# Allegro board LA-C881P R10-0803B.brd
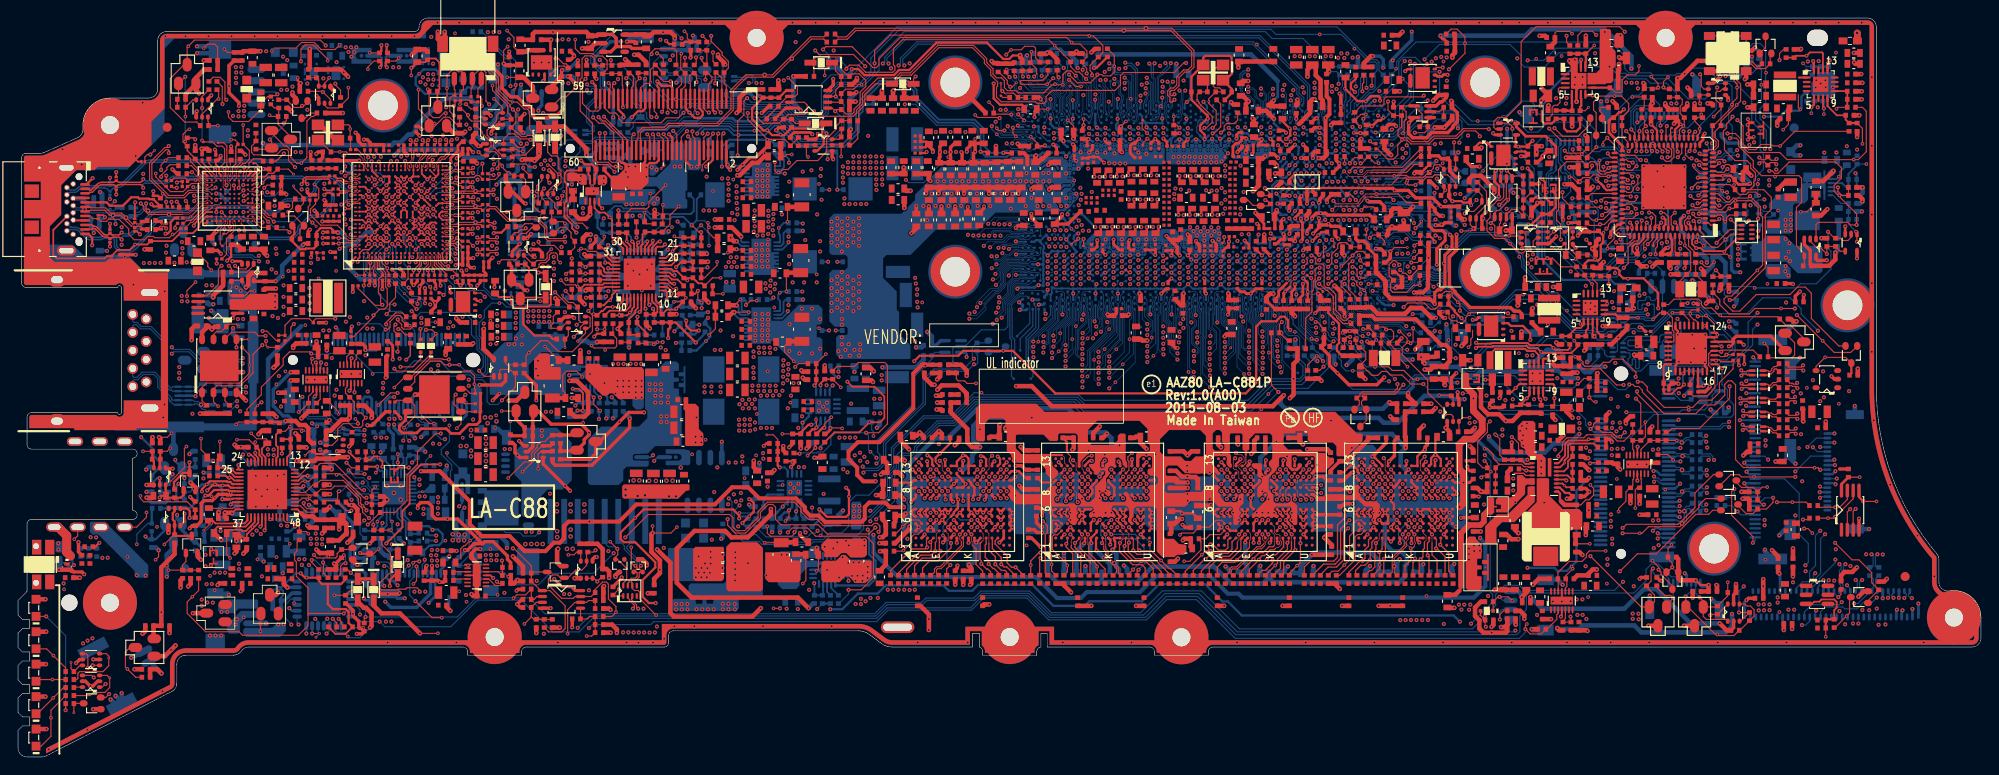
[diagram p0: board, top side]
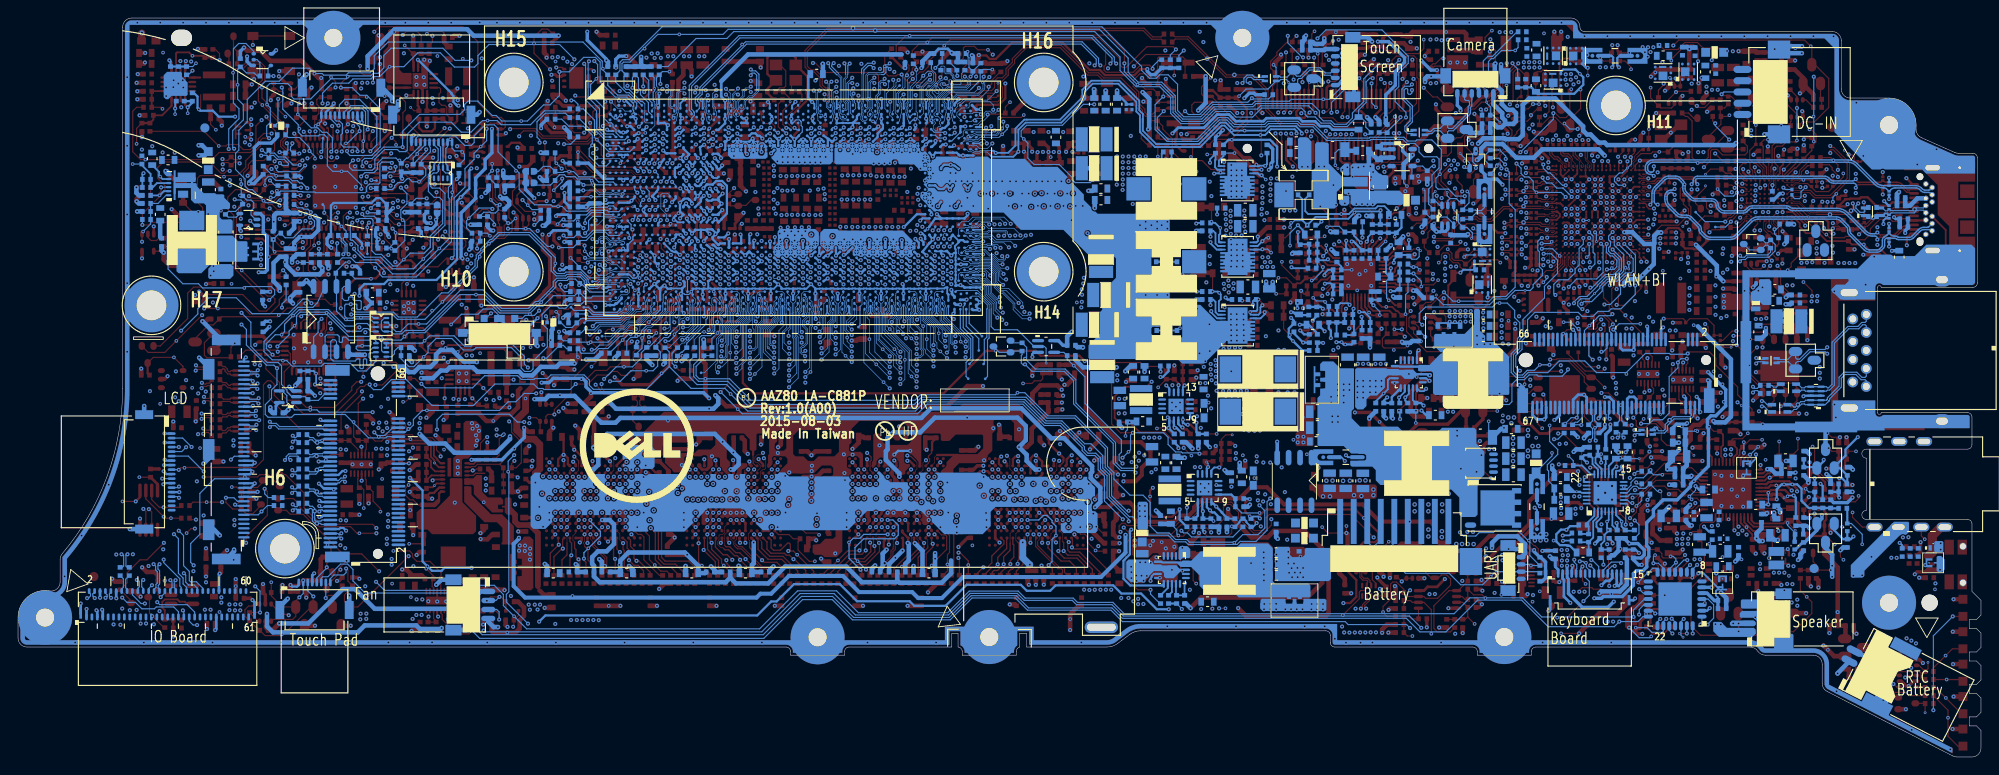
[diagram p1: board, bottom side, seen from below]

Outline 217.81 x 82 mm; copper layers: TOP, GND1, IN1, GND2, IN2, IN3, VCC, IN4, GND3, BOTTOM. Coordinates in mm from the lower left corner of the outline.
Outline path: 0,17.38 1,18.38 1,25.86 arc(1.15,26.21) 1.5,26.36 12.72,26.36 arc(13.22,26.86) 12.72,27.36 12.72,33.16 arc(13.22,33.66) 12.72,34.16 1.5,34.16 arc(1.15,34.31) 1,34.66 1,37.71 arc(1.15,38.06) 1.5,38.21 11.07,38.21 arc(11.27,38.01) 11.47,38.21 11.47,52.11 arc(11.27,52.31) 11.07,52.11 0.9,52.11 arc(0.55,52.26) 0.4,52.61 0.4,66.49 arc(0.55,66.84) 0.9,66.99 2.49,66.99 arc(2.7,67.01) 2.9,67.08 6.61,68.73 arc(7.04,69.09) 7.2,69.64 7.2,70.12 arc(8.08,72.24) 10.2,73.12 14.5,73.12 arc(15.21,73.41) 15.5,74.12 15.5,79.5 arc(15.79,80.21) 16.5,80.5 44,80.5 arc(44.35,80.65) 44.5,81 arc(44.79,81.71) 45.5,82 205.2,82 arc(205.91,81.71) 206.2,81 206.2,40.92 arc(207.93,31.15) 212.9,22.56 arc(213.08,22.26) 213.14,21.91 213.14,19.41 arc(213.49,18.65) 214.31,18.43 arc(216.75,17.76) 217.81,15.47 217.81,13.2 arc(217.52,12.49) 216.81,12.2 132.59,12.2 arc(132.24,12.05) 132.09,11.7 132.09,11.3 126.09,11.3 126.09,11.7 arc(125.94,12.05) 125.59,12.2 114.2,12.2 114.2,13.7 113.5,13.7 113.5,12.2 arc(113.17,12.04) 113.04,11.7 113.04,11.3 107.04,11.3 107.04,11.72 arc(106.94,12.02) 106.68,12.2 106.68,13.7 105.88,13.7 105.88,12.2 96.99,12.2 arc(96.36,12.3) 95.79,12.6 94.46,13.6 arc(93.89,13.9) 93.26,14 72.7,14 arc(72.35,13.85) 72.2,13.5 72.2,12.7 arc(72.05,12.35) 71.7,12.2 56.39,12.2 arc(56.04,12.05) 55.89,11.7 55.89,11.3 49.89,11.3 49.89,11.7 arc(49.74,12.05) 49.39,12.2 25.61,12.2 arc(25.14,12.08) 24.78,11.75 arc(24.41,11.42) 23.94,11.3 18.62,11.3 arc(17.91,11.01) 17.62,10.3 17.62,8.17 arc(17.47,7.65) 17.08,7.28 3.12,0.11 arc(2.89,0.03) 2.66,0 1,0 arc(0.29,0.29) 0,1 0,2.95 0.5,3.45 1.3,3.45 1.3,4.45 0.5,4.45 0,4.95 0,6.55 0.5,7.05 1.3,7.05 1.3,8.05 0.5,8.05 0,8.55 0,10.15 0.5,10.65 1.3,10.65 1.3,11.65 0.5,11.65 0,12.15 0,13.75 0.5,14.25 1.3,14.25 1.3,15.25 0.5,15.25 0,15.75 0,17.38

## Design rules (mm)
constraint set DEFAULT: min track width 0.127
net group 12C: nets I2C1_SDA I2C1_SDA_TP
net group CLK1_PCIE_WLAN: nets CLK1_PCIE_WLAN CLK1_PCIE_WLAN#
net group CLK_ITPXDP: nets CLK_ITPXDP_N CLK_ITPXDP_P
net group CLK_PCIE_MMI: nets CLK_PCIE_MMI CLK_PCIE_MMI#
net group CLK_PCIE_SSD: nets CLK_PCIE_SSD CLK_PCIE_SSD#
net group CLKO_PCIE_TBT: nets CLK0_PCIE_TBT CLK0_PCIE_TBT#
net group CPU_DDI1_AUX: nets CPU_DDI1_AUXN CPU_DDI1_AUXP
net group CPU_DDI2_AUX: nets CPU_DDI2_AUXN CPU_DDI2_AUXP
net group DDI1_PTX_TBRX_P0: nets DDI1_PTX_TBRX_N0 DDI1_PTX_TBRX_P0
net group DDI1_PTX_TBRX_P1: nets DDI1_PTX_TBRX_N1 DDI1_PTX_TBRX_P1
net group DDI1_PTX_TBRX_P2: nets DDI1_PTX_TBRX_N2 DDI1_PTX_TBRX_P2
net group DDI1_PTX_TBRX_P3: nets DDI1_PTX_TBRX_N3 DDI1_PTX_TBRX_P3
net group DDI2_PTX_TBRX_P0: nets DDI2_PTX_TBRX_N0 DDI2_PTX_TBRX_P0
net group DDI2_PTX_TBRX_P1: nets DDI2_PTX_TBRX_N1 DDI2_PTX_TBRX_P1
net group DDI2_PTX_TBRX_P2: nets DDI2_PTX_TBRX_N2 DDI2_PTX_TBRX_P2
net group DDI2_PTX_TBRX_P3: nets DDI2_PTX_TBRX_N3 DDI2_PTX_TBRX_P3
net group DIFFPAIR0: nets EDP_AUXN EDP_AUXP
net group DIFFPAIR1: nets EDP_AUXN_C EDP_AUXP_C
net group DIFFPAIR2: nets EDP_AUXN_CONN EDP_AUXP_CONN
net group DIFFPAIR4: nets EDP_TXN_P2_C EDP_TXP_P2_C
net group DIFFPAIR5: nets EDP_TXN_P3_C EDP_TXP_P3_C
net group DIFFPAIR6: nets CPU_DDI1_AUXN_C CPU_DDI1_AUXP_C
net group DIFFPAIR7: nets CLK_ITPXDP_N_R CLK_ITPXDP_P_R
net group DIFFPAIR8: nets PCIE_PRX_TBTX_N1_C PCIE_PRX_TBTX_P1_C
net group DIFFPAIR9: nets PCIE_PRX_TBTX_N2_C PCIE_PRX_TBTX_P2_C
net group DIFFPAIR10: nets PCIE_PTX_CARDRX_N6_C PCIE_PTX_CARDRX_P6_C
net group DIFFPAIR11: nets PCIE_PTX_SSDRX_N11_C PCIE_PTX_SSDRX_P11_C
net group DIFFPAIR12: nets PCIE_PTX_SSDRX_N10_C PCIE_PTX_SSDRX_P10_C
net group DIFFPAIR13: nets PCIE_PTX_WLANRX_N5_C PCIE_PTX_WLANRX_P5_C
net group DIFFPAIR14: nets PCIE_PTX_SSDRX_N9_C PCIE_PTX_SSDRX_P9_C
net group DIFFPAIR15: nets PCIE_PTX_TBRX_N1_C PCIE_PTX_TBRX_P1_C
net group DIFFPAIR16: nets PCIE_PTX_TBRX_N2_C PCIE_PTX_TBRX_P2_C
net group DIFFPAIR17: nets USB20_N2_CONN USB20_P2_CONN
net group DIFFPAIR18: nets USB20_N3_R USB20_P3_R
net group DIFFPAIR19: nets USB20_N4_CONN USB20_P4_CONN
net group DIFFPAIR20: nets USB20_N5_CONN USB20_P5_CONN
net group DIFFPAIR21: nets USB3RN2_RC_CON USB3RP2_RC_CON
net group DIFFPAIR22: nets USB3TN2_C USB3TP2_C
net group DIFFPAIR23: nets USB3TN2_RC_CON USB3TP2_RC_CON
net group DIFFPAIR24: nets EDP_TXN_P0_C EDP_TXP_P0_C
net group DIFFPAIR25: nets EDP_TXN_P1_C EDP_TXP_P1_C
net group DP_CPU_DDI2_AUXN_C: nets CPU_DDI2_AUXN_C CPU_DDI2_AUXP_C
net group DP_EDP_TXN_P0_CONN: nets EDP_TXN_P0_CONN EDP_TXP_P0_CONN
net group DP_EDP_TXN_P1_CONN: nets EDP_TXN_P1_CONN EDP_TXP_P1_CONN
net group DP_EDP_TXN_P2_CONN: nets EDP_TXN_P2_CONN EDP_TXP_P2_CONN
net group DP_EDP_TXN_P3_CONN: nets EDP_TXN_P3_CONN EDP_TXP_P3_CONN
net group DP_TBT_I2C_B_N_R: nets TBT_I2C_B_N_R TBT_I2C_B_P_R
net group DP_TBT_USB2_T_N_R: nets TBT_USB2_T_N_R TBT_USB2_T_P_R
net group EDP_TX_P1: nets EDP_TXN_P1 EDP_TXP_P1
net group EDP_TX_P2: nets EDP_TXN_P2 EDP_TXP_P2
net group EDP_TX_P3: nets EDP_TXN_P3 EDP_TXP_P3
net group EPD_TX_P0: nets EDP_TXN_P0 EDP_TXP_P0
net group MEM_SMBCLKDATA: nets MEM_SMBCLK MEM_SMBDATA
net group PBAT_SMBCLKDAT: nets PBAT_SMBCLK PBAT_SMBDAT
net group PCIE_PRX_CARDTX_P6: nets PCIE_PRX_CARDTX_N6 PCIE_PRX_CARDTX_P6
net group PCIE_PRX_SSDTX_11: nets PCIE_PRX_SSDTX_N11 PCIE_PRX_SSDTX_P11
net group PCIE_PRX_SSDTX_P9: nets PCIE_PRX_SSDTX_N9 PCIE_PRX_SSDTX_P9
net group PCIE_PRX_SSDTX_P10: nets PCIE_PRX_SSDTX_N10 PCIE_PRX_SSDTX_P10
net group PCIE_PRX_TBTX_P1: nets PCIE_PRX_TBTX_N1 PCIE_PRX_TBTX_P1
net group PCIE_PRX_TBTX_P2: nets PCIE_PRX_TBTX_N2 PCIE_PRX_TBTX_P2
net group PCIE_PRX_WLANTX_P5: nets PCIE_PRX_WLANTX_N5 PCIE_PRX_WLANTX_P5
net group PCIE_PTX_CARDRX_P6: nets PCIE_PTX_CARDRX_N6 PCIE_PTX_CARDRX_P6
net group PCIE_PTX_SSDRX_11: nets PCIE_PTX_SSDRX_N11 PCIE_PTX_SSDRX_P11
net group PCIE_PTX_SSDRX_P9: nets PCIE_PTX_SSDRX_N9 PCIE_PTX_SSDRX_P9
net group PCIE_PTX_SSDRX_P10: nets PCIE_PTX_SSDRX_N10 PCIE_PTX_SSDRX_P10
net group PCIE_PTX_TBRX_P1: nets PCIE_PTX_TBRX_N1 PCIE_PTX_TBRX_P1
net group PCIE_PTX_TBRX_P2: nets PCIE_PTX_TBRX_N2 PCIE_PTX_TBRX_P2
net group PCIE_PTX_WLANRX_P5: nets PCIE_PTX_WLANRX_N5 PCIE_PTX_WLANRX_P5
net group REM_DIODE1: nets REM_DIODE1_N REM_DIODE1_P
net group REM_DIODE2: nets REM_DIODE2_N REM_DIODE2_P
net group REM_DIODE3: nets REM_DIODE3_N REM_DIODE3_P
net group REM_DIODE4: nets REM_DIODE4_N REM_DIODE4_P
net group SATA_PRX_SSDTX_2: nets SATA_PRX_SSDTX_N2 SATA_PRX_SSDTX_P2
net group SATA_PTX_SSDRX_2: nets SATA_PTX_SSDRX_N2 SATA_PTX_SSDRX_P2
net group SMB_CLKDAT: nets CLK_SMB DAT_SMB
net group SML1_SMBCLKDAT: nets SML1_SMBCLK SML1_SMBDAT
net group SPACING-18: nets PECI_EC PECI_EC_R
net group TBT_12C_CLKDATA: nets TBT_I2C_CLK TBT_I2C_DATA
net group TBT_I2C_B: nets TBT_I2C_B_N TBT_I2C_B_P
net group TBT_USB2_T: nets TBT_USB2_T_N TBT_USB2_T_P
net group TBT_USB3_RX1: nets TBT_USB3_RX1_N TBT_USB3_RX1_P
net group TBT_USB3_TX1: nets TBT_USB3_TX1_N TBT_USB3_TX1_P
net group TBT_USB3_TXO_P: nets TBT_USB3_TX0_N TBT_USB3_TX0_P
net group USB2.0_P1: nets USB20_N1 USB20_P1
net group USB2.0_P2: nets USB20_N2 USB20_P2
net group USB2.0_P3: nets USB20_N3 USB20_P3
net group USB2.0_P4: nets USB20_N4 USB20_P4
net group USB2.0_P5: nets USB20_N5 USB20_P5
net group USB3.0_R1: nets USB3RN1 USB3RP1
net group USB3.0_R2: nets USB3RN2 USB3RP2
net group USB3.0_T1: nets USB3TN1 USB3TP1
net group USB3.0_T2: nets USB3TN2 USB3TP2
net group USB_2.0: nets TBT_USB2_D_N TBT_USB2_D_P
net group 12C_15: nets HDA_BIT_CLK HDA_BIT_CLK_R I2C1_SCK I2C1_SCK_TP PCH_SPI_CLK PCH_SPI_CLK_TPM SPI_CLK_VROM
net group 24MHZ: nets CLK_LPC_DEBUG CLK_PCI_MEC PCI_CLK_LPC0 PCI_CLK_LPC1 XTAL24_IN XTAL24_OUT
net group AR_TBT: nets TBT_USB3_TX0_N_C TBT_USB3_TX0_P_C TBT_USB3_TX1_N_C TBT_USB3_TX1_P_C
net group COMP-20-25: nets SM_RCOMP0 SM_RCOMP1 SM_RCOMP2
net group DDRA_CKE: nets DDR_A_CKE0 DDR_A_CKE1 DDR_A_CKE2 DDR_A_CKE3
net group DDRB-D6: nets DDR_B_D48 DDR_B_D49 DDR_B_D50 DDR_B_D51 DDR_B_D52 DDR_B_D53 DDR_B_D54 DDR_B_D55
net group DDRB-D7: nets DDR_B_D56 DDR_B_D57 DDR_B_D58 DDR_B_D59 DDR_B_D60 DDR_B_D61 DDR_B_D62 DDR_B_D63
net group DDRB_CKE: nets DDR_B_CKE0 DDR_B_CKE1 DDR_B_CKE2 DDR_B_CKE3
net group DP1_AR_TBT: nets DDI1_PTX_TBRX_N0_C DDI1_PTX_TBRX_N1_C DDI1_PTX_TBRX_N2_C DDI1_PTX_TBRX_N3_C DDI1_PTX_TBRX_P0_C DDI1_PTX_TBRX_P1_C DDI1_PTX_TBRX_P2_C DDI1_PTX_TBRX_P3_C
net group DP2_AR_TBT: nets DDI2_PTX_TBRX_N0_C DDI2_PTX_TBRX_N1_C DDI2_PTX_TBRX_N2_C DDI2_PTX_TBRX_N3_C DDI2_PTX_TBRX_P0_C DDI2_PTX_TBRX_P1_C DDI2_PTX_TBRX_P2_C DDI2_PTX_TBRX_P3_C
net group HDA: nets HDA_SDIN0 HDA_SDOUT HDA_SDOUT_R HDA_SYNC HDA_SYNC_R
net group R_DDRA-CLK-UD19: nets DDR_A_DQS0 DDR_A_DQS1 DDR_A_DQS2 DDR_A_DQS3
net group R_DDRA-CLK-UD20: nets DDR_A_DQS4 DDR_A_DQS5 DDR_A_DQS6 DDR_A_DQS7
net group R_DDRA-D0: nets DDR_A_D0 DDR_A_D1 DDR_A_D2 DDR_A_D3 DDR_A_D4 DDR_A_D5 DDR_A_D6 DDR_A_D7
net group R_DDRA-D1: nets DDR_A_D8 DDR_A_D9 DDR_A_D10 DDR_A_D11 DDR_A_D12 DDR_A_D13 DDR_A_D14 DDR_A_D15
net group R_DDRA-D2: nets DDR_A_D16 DDR_A_D17 DDR_A_D18 DDR_A_D19 DDR_A_D20 DDR_A_D21 DDR_A_D22 DDR_A_D23
net group R_DDRA-D3: nets DDR_A_D24 DDR_A_D25 DDR_A_D26 DDR_A_D27 DDR_A_D28 DDR_A_D29 DDR_A_D30 DDR_A_D31
net group R_DDRA-D4: nets DDR_A_D32 DDR_A_D33 DDR_A_D34 DDR_A_D35 DDR_A_D36 DDR_A_D37 DDR_A_D38 DDR_A_D39
net group R_DDRA-D5: nets DDR_A_D40 DDR_A_D41 DDR_A_D42 DDR_A_D43 DDR_A_D44 DDR_A_D45 DDR_A_D46 DDR_A_D47
net group R_DDRA-D6: nets DDR_A_D48 DDR_A_D49 DDR_A_D50 DDR_A_D51 DDR_A_D52 DDR_A_D53 DDR_A_D54 DDR_A_D55
net group R_DDRA-D7: nets DDR_A_D56 DDR_A_D57 DDR_A_D58 DDR_A_D59 DDR_A_D60 DDR_A_D61 DDR_A_D62 DDR_A_D63
net group R_DDRA-DQS0: nets DDR_A_DQS#0
net group R_DDRA-DQS1: nets DDR_A_DQS#1
net group R_DDRA-DQS2: nets DDR_A_DQS#2
net group R_DDRA-DQS3: nets DDR_A_DQS#3
net group R_DDRA-DQS4: nets DDR_A_DQS#4
net group R_DDRA-DQS5: nets DDR_A_DQS#5
net group R_DDRA-DQS6: nets DDR_A_DQS#6
net group R_DDRA-DQS7: nets DDR_A_DQS#7
net group R_DDRB-CLK-UD21: nets DDR_B_DQS0 DDR_B_DQS1 DDR_B_DQS2 DDR_B_DQS3
net group R_DDRB-CLK-UD22: nets DDR_B_DQS4 DDR_B_DQS5 DDR_B_DQS6 DDR_B_DQS7
net group R_DDRB-D0: nets DDR_B_D0 DDR_B_D1 DDR_B_D2 DDR_B_D3 DDR_B_D4 DDR_B_D5 DDR_B_D6 DDR_B_D7
net group R_DDRB-D1: nets DDR_B_D8 DDR_B_D9 DDR_B_D10 DDR_B_D11 DDR_B_D12 DDR_B_D13 DDR_B_D14 DDR_B_D15
net group R_DDRB-D2: nets DDR_B_D16 DDR_B_D17 DDR_B_D18 DDR_B_D19 DDR_B_D20 DDR_B_D21 DDR_B_D22 DDR_B_D23
net group R_DDRB-D3: nets DDR_B_D24 DDR_B_D25 DDR_B_D26 DDR_B_D27 DDR_B_D28 DDR_B_D29 DDR_B_D30 DDR_B_D31
net group R_DDRB-D4: nets DDR_B_D32 DDR_B_D33 DDR_B_D34 DDR_B_D35 DDR_B_D36 DDR_B_D37 DDR_B_D38 DDR_B_D39
net group R_DDRB-D5: nets DDR_B_D40 DDR_B_D41 DDR_B_D42 DDR_B_D43 DDR_B_D44 DDR_B_D45 DDR_B_D46 DDR_B_D47
net group R_DDRB-DQS0: nets DDR_B_DQS#0
net group R_DDRB-DQS1: nets DDR_B_DQS#1
net group R_DDRB-DQS2: nets DDR_B_DQS#2
net group R_DDRB-DQS3: nets DDR_B_DQS#3
net group R_DDRB-DQS4: nets DDR_B_DQS#4
net group R_DDRB-DQS5: nets DDR_B_DQS#5
net group R_DDRB-DQS6: nets DDR_B_DQS#6
net group R_DDRB-DQS7: nets DDR_B_DQS#7
net group SPACING-12: nets H_CATERR# H_PROCHOT# H_PROCHOT#_EC H_PROCHOT#_R H_THERMTRIP# H_VCCST_PWRGD PCIE_RCOMPN PCIE_RCOMPP VCCST_PWRGD XDP_OBS0 XDP_OBS0_R XDP_OBS1 XDP_OBS1_R XDP_OBS2_R XDP_OBS3_R
net group SPACING-15: nets DMIC_CLK_CODEC DMIC_CLK_CODEC_R PCH_RTCRST# PCH_RTCX1 PCH_RTCX2 SRTCRST# USBCOMP XCLK_BIASREF
net group SPACING-20: nets +V_DDR_REF_CA +V_DDR_REFA_R +V_DDR_REFB_R +VREFDQ_A +VREFDQ_B N40373163 N40373501 N40376778
net group SPACING-25: nets EDP_COMP
net group SPI_PCH: nets PCH_SPI_CS0# PCH_SPI_DO2_XDP PCH_SPI_DO_XDP PCH_SPI_IO2 PCH_SPI_IO3 PCH_SPI_SI PCH_SPI_SI_TPM PCH_SPI_SO PCH_SPI_SO_TPM RESET_OUT#_R SPI_IO2_VROM SPI_IO3_VROM SPI_SI_VROM SPI_SO_VROM
net group UART: nets UART0_TX
net group W20: nets +3V_VC +AVDD2 +DVDD ALW_PWRGD_3V_5V BATBTN# BATDRV#
nets with their own width: min track width 0.127; nets +1.8VA +3VLP +3VS_AUDIO
nets with their own width: min track width 0.508; nets GND

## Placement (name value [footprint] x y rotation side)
C2  15P_0402_50V8J  [C_0402]  27.28 50.94 90 top
C3  15P_0402_50V8J  [C_0402]  20.09 51.27 0 bottom
C4  15P_0402_50V8J  [C_0402]  54.45 70.27 0 bottom
C5  15P_0402_50V8J  [C_0402]  74.4 78.44 0 bottom
C6  15P_0402_50V8J  [C_0402]  193.09 33.87 180 top
C7  15P_0402_50V8J  [C_0402]  186.74 18.37 180 top
C8  2.2U_0603_6.3V6K~D  [C_0603]  63.48 80.03 270 top
C94  10U_0603_6.3V6M  [C_0603]  181.46 44.54 180 top
C95  0.1U_0201_10V6K  [C_0201]  186.41 41.11 270 top
C96  0.1U_0201_10V6K  [C_0201]  190.31 46.06 0 top
C97  0.1U_0201_10V6K  [C_0201]  181.17 47.23 180 top
C98  0.1U_0201_10V6K  [C_0201]  182.6 40.73 0 top
C135  0.1U_0201_10V6K  [C_0201]  190.31 44.66 0 top
C265  .1U_0402_16V7K~D  [C_0402]  20.09 50.38 0 bottom
C303  150U_B2_6.3VM_ESR35M  [C_B2]  19.94 48.35 180 bottom
C352  0.1U_0402_10V7K  [C_0402]  46.63 16.85 0 top
C355  2200P_0402_25V7K~D  [C_0402]  48.31 19.59 180 top
C375  0.1U_0402_25V6K~D  [C_0402]  45.95 20.48 270 top
C376  0.1U_0402_25V6K~D  [C_0402]  47.22 21.98 90 bottom
C377  0.1U_0402_25V6K~D  [C_0402]  45.06 20.48 270 top
C397  0.47U_0402_25V6K  [C_0402]  9.32 61.17 180 bottom
C398  0.47U_0402_25V6K  [C_0402]  9.02 58.82 180 bottom
C401  0.47U_0402_25V6K  [C_0402]  9.02 59.71 180 bottom
C402  0.47U_0402_25V6K  [C_0402]  9.32 62.06 180 bottom
C612  0.1U_0402_25V6K~D  [C_0402]  196.2 25.1 90 top
C613  0.1U_0402_25V6K~D  [C_0402]  199.67 15.2 0 top
C614  0.1U_0402_25V6K~D  [C_0402]  197.21 50.5 0 top
C615  0.1U_0402_25V6K~D  [C_0402]  196.06 52.54 180 top
C616  0.1U_0402_25V6K~D  [C_0402]  190.63 48.09 270 bottom
C617  0.1U_0402_25V6K~D  [C_0402]  190.67 50.71 90 bottom
C618  0.22U_0201_6.3V6M  [C_0201]  18.29 59.81 180 top
C621  0.1U_0402_10V7K  [C_0402]  24.49 40.34 180 bottom
C623  0.1U_0402_10V7K  [C_0402]  24.49 41.23 180 bottom
C712  22U_0603_6.3V6M~D  [C_0603]  33.12 46.82 270 top
C713  0.1U_0402_10V7K  [C_0402]  48.87 46.69 270 top
C715  0.1U_0402_10V7K  [C_0402]  31.09 46.82 270 top
C716  22U_0603_6.3V6M~D  [C_0603]  47.73 46.69 270 top
C719  4.7U_0603_6.3V6K  [C_0603]  175.43 25.61 180 top
C720  .1U_0402_16V7K~D  [C_0402]  175.18 28.03 180 top
C721  0.01U_0402_16V7K~D  [C_0402]  176.12 41.55 180 top
C722  47P_0402_50V8J~D  [C_0402]  175.18 26.76 180 top
C962  10U_0603_6.3V6M~D  [C_0603]  26.14 50.06 270 top
C963  .1U_0402_16V7K~D  [C_0402]  27.28 50.07 270 top
C1060  0.1U_0402_10V7K  [C_0402]  196.32 37.42 180 top
C1061  0.1U_0402_10V7K  [C_0402]  196.32 39.2 180 top
C1062  0.1U_0402_10V7K  [C_0402]  196.32 38.31 180 top
C1063  0.1U_0402_10V7K  [C_0402]  196.32 40.09 180 top
C1064  0.1U_0402_10V7K  [C_0402]  196.32 36.53 180 top
C1065  0.1U_0402_10V7K  [C_0402]  196.32 35.65 180 top
C1066  0.1U_0402_10V7K  [C_0402]  196.32 41.87 180 top
C1067  0.1U_0402_10V7K  [C_0402]  196.32 40.98 180 top
C1068  0.1U_0402_10V7K  [C_0402]  196.32 43.65 180 top
C1069  0.1U_0402_10V7K  [C_0402]  196.32 42.76 180 top
C1102  0.1U_0402_25V6K~D  [C_0402]  166.17 15.33 180 top
C1143  10U_0603_6.3V6M~D  [C_0603]  195.81 34.18 270 top
C1145  .1U_0402_16V7K~D  [C_0402]  193.09 34.76 180 top
C1158  1U_0402_6.3V6K~D  [C_0402]  177.52 33.44 270 top
C1159  0.1U_0402_10V7K  [C_0402]  167.82 17.1 180 top
C1160  1U_0402_6.3V6K~D  [C_0402]  37.82 39.91 270 top
C1161  0.1U_0402_10V7K  [C_0402]  181.79 26.88 180 top
C1162  1U_0402_6.3V6K~D  [C_0402]  181.97 33.56 270 top
C1163  1000P_0402_50V7K~D  [C_0402]  179.93 29.88 270 top
C1164  0.1U_0402_10V7K  [C_0402]  176.25 31.76 90 top
C1166  1U_0402_6.3V6K~D  [C_0402]  35.79 39.91 270 top
C1167  2200P_0402_25V7K~D  [C_0402]  36.99 44.93 90 top
C1168  1U_0402_6.3V6K~D  [C_0402]  198.02 39.56 270 top
C1169  1U_0402_6.3V6K~D  [C_0402]  30.96 42.71 270 top
C1199  1U_0402_6.3V6K~D  [C_0402]  51.23 22.31 180 top
C1200  0.1U_0402_10V7K  [C_0402]  47.14 22.89 0 top
C1201  1U_0402_6.3V6K~D  [C_0402]  51.87 17.87 180 top
C1203  1U_0402_6.3V6K~D  [C_0402]  60.35 78.32 0 top
C1204  0.1U_0402_10V7K  [C_0402]  60.3 75.51 0 top
C1205  2.2U_0603_6.3V6K~D  [C_0603]  24.28 28 0 bottom
C1208  0.1U_0402_10V7K  [C_0402]  57.13 79.59 0 top
C1211  0.1U_0402_10V7K  [C_0402]  199.67 36.53 0 top
C1212  1000P_0402_50V7K~D  [C_0402]  33.12 39.28 270 top
C1213  1U_0402_6.3V6K~D  [C_0402]  34.21 44.41 180 top
C1214  4700P_0402_25V7K  [C_0402]  32.23 39.28 270 top
C1215  0.1U_0402_10V7K  [C_0402]  34.27 46.64 270 top
C1216  0.1U_0402_10V7K  [C_0402]  41 45.22 90 top
C1217  0.1U_0402_10V7K  [C_0402]  29.57 39.51 90 top
C1218  0.1U_0402_10V7K  [C_0402]  34.27 37.12 270 top
C1220  1U_0402_6.3V6K  [C_0402]  54.5 76.76 90 top
C1221  1U_0402_6.3V6K~D  [C_0402]  54.45 69.31 0 bottom
C1222  1U_0402_6.3V6K~D  [C_0402]  74.4 79.33 0 bottom
C1223  1U_0402_6.3V6K~D  [C_0402]  68.56 80.17 270 top
C1225  1U_0402_6.3V6K~D  [C_0402]  187.6 18.37 0 top
C1226  680P_0402_50V7K~D  [C_0402]  181.84 19.01 90 top
C1229  680P_0402_50V7K~D  [C_0402]  180.7 19.01 90 top
C1254  1U_0402_6.3V6K~D  [C_0402]  169.14 16.21 270 top
C1256  1U_0402_6.3V6K~D  [C_0402]  173.2 14.97 270 top
C1257  2200P_0402_25V7K~D  [C_0402]  170.87 19.77 180 top
C1258  2200P_0402_25V7K~D  [C_0402]  171.73 19.77 0 top
C1264  0.1U_0402_10V7K  [C_0402]  175.18 20.15 180 top
C1273  0.1U_0402_25V6K~D  [C_0402]  69.84 38.88 180 bottom
C1274  0.1U_0402_25V6K~D  [C_0402]  58.84 57.03 90 bottom
C1275  0.1U_0402_25V6K~D  [C_0402]  73.19 39.65 0 top
C1278  220P_0402_50V8K  [C_0402]  48.31 20.48 180 top
C1279  220P_0402_50V8K  [C_0402]  15.8 61.1 90 top
C1280  220P_0402_50V8K  [C_0402]  14.71 57.25 270 top
C1289  0.1U_0402_10V7K  [C_0402]  27.41 52.79 90 top
C1292  2200P_0402_25V7K~D  [C_0402]  178.92 29.88 270 top
C1293  2200P_0402_25V7K~D  [C_0402]  37.88 44.93 90 top
C1297  15P_0402_50V8J  [C_0402]  31.98 46.82 270 top
C1298  15P_0402_50V8J  [C_0402]  49.76 46.69 270 top
C1301  15P_0402_50V8J  [C_0402]  43.54 36.86 270 bottom
C1302  15P_0402_50V8J  [C_0402]  42.39 36.86 270 bottom
C1304  15P_0402_50V8J  [C_0402]  176.12 40.66 180 top
C1309  15P_0402_50V8J  [C_0402]  15.9 14.56 0 top
C1321  1U_0402_6.3V6K~D  [C_0402]  193.65 17.61 180 top
C1322  0.1U_0402_10V7K  [C_0402]  195.94 14.82 0 top
C1324  0.1U_0402_10V7K  [C_0402]  195.3 21.09 90 top
C1325  1U_0402_6.3V6K~D  [C_0402]  196.95 21.09 90 top
C1339  1U_0603_25V6  [C_0603]  20.23 57.24 180 top
C1341  4.7U_0603_25V6K  [C_0603]  27.79 61.17 0 top
C1345  1U_0201_6.3V6M  [C_0201]  20.42 66.25 90 top
C1346  10U_0402_6.3V6M  [C_0402]  20.88 47.84 180 top
C1347  22U_0603_6.3V6M  [C_0603]  21.34 57.61 270 top
C1348  22U_0603_6.3V6M  [C_0603]  24.84 57.74 270 top
C1349  22U_0603_6.3V6M  [C_0603]  27.28 57.74 270 top
C1350  22U_0603_6.3V6M  [C_0603]  26.06 57.74 270 top
C1353  1U_0603_25V6  [C_0603]  18.07 55.08 180 top
C1354  1U_0201_6.3V6M  [C_0201]  21.95 66.21 90 top
C2973  0.1U_0402_16V4Z  [C_0402]  14.66 9.74 180 top
C2982  10U_0603_25V6M  [C_0603]  197.27 24.54 90 top
C2983  0.1U_0402_10V7K  [C_0402]  5.23 19.9 0 top
CA2  10U_0805_10V6K  [C_0805]  28.08 22.82 0 bottom
CA3  0.1U_0402_16V7K~N  [C_0402]  26.9 23.28 270 bottom
CA4  0.1U_0402_16V7K~N  [C_0402]  33.12 26.32 270 top
CA5  10U_0805_10V6K  [C_0805]  35.95 26.37 0 top
CA6  10U_0805_10V6K  [C_0805]  32.65 33.36 0 bottom
CA7  0.1U_0402_16V7K~N  [C_0402]  33.05 31.96 0 bottom
CA23  10P_0402_50V8J~D  [C_0402]  36.37 28.28 180 top
CA24  10P_0402_50V8J~D  [C_0402]  33.96 32.09 180 top
CA25  10P_0402_50V8J~D  [C_0402]  33.96 27.39 180 top
CA27  10P_0402_50V8J~D  [C_0402]  33.96 29.17 180 top
CA28  100P_0402_50V8J~D  [C_0402]  6.96 23.15 270 bottom
CA29  100P_0402_50V8J~D  [C_0402]  19.69 22.89 90 bottom
CA30  10P_0402_50V8J~D  [C_0402]  33.96 30.18 180 top
CA31  0.1U_0402_10V7K  [C_0402]  34.9 26.32 270 top
CA32  100P_0402_50V8J~D  [C_0402]  111.86 76.08 90 bottom
CA33  100P_0402_50V8J~D  [C_0402]  28.07 37.17 90 top
CA34  0.1U_0402_10V7K  [C_0402]  28.99 37.05 270 top
CA35  100P_0402_50V8J~D  [C_0402]  111.81 73.19 0 top
CA40  0.1U_0402_25V6K~D  [C_0402]  15.79 33.92 90 top
CA42  2.2U_0402_6.3V6M  [C_0402]  34.01 26.32 270 top
CA53  1000P_0402_50V7K~D  [C_0402]  24.87 19.26 0 top
CA54  1000P_0402_50V7K~D  [C_0402]  28.63 19.77 180 top
CA55  1000P_0402_50V7K~D  [C_0402]  22.96 19.26 0 top
CA56  1000P_0402_50V7K~D  [C_0402]  29.49 19.77 0 top
CA68  100P_0402_50V8J~D  [C_0402]  7.09 22.39 270 top
CA69  100P_0402_50V8J~D  [C_0402]  14.83 24.16 270 bottom
CA70  4.7U_0402_6.3V6M  [C_0402]  19.66 28.36 270 top
CA71  4.7U_0402_6.3V6M  [C_0402]  18.45 30.32 270 bottom
CA72  4.7U_0402_6.3V6M  [C_0402]  182.6 41.49 0 top
CA74  10U_0603_6.3V6M~D  [C_0603]  16.42 28.98 180 top
CA78  0.1U_0402_10V7K  [C_0402]  23.14 26.46 180 top
CA80  0.1U_0402_10V7K  [C_0402]  25.38 24.16 270 top
CA82  10U_0603_6.3V6M~D  [C_0603]  24.23 24.66 270 top
CA83  10U_0603_6.3V6M~D  [C_0603]  22.71 26.44 90 bottom
CA86  2.2U_0603_6.3V6K~D  [C_0603]  21.18 26.22 90 top
CA87  2.2U_0402_6.3V6M  [C_0402]  22.15 31.2 180 top
CA97  0.1U_0402_16V7K~N  [C_0402]  32.74 27.21 270 bottom
CA98  10U_0805_10V6K  [C_0805]  33.8 26.76 0 bottom
CA99  10U_0805_10V6K  [C_0805]  30.46 26.54 90 bottom
CA100  0.1U_0402_16V7K~N  [C_0402]  29.06 26.3 90 bottom
CA101  10U_0805_10V6K  [C_0805]  21.73 24.6 0 bottom
CA102  10U_0805_10V6K  [C_0805]  22.54 32.85 180 bottom
CA103  0.1U_0402_16V7K~N  [C_0402]  22.15 31.45 180 bottom
CA104  0.1U_0402_10V7K  [C_0402]  33.05 31.07 0 bottom
CA105  2.2U_0402_6.3V6M  [C_0402]  33.05 30.18 0 bottom
CA106  0.1U_0402_10V7K  [C_0402]  30.25 35.26 0 top
CA107  10U_0603_6.3V6M~D  [C_0603]  27.66 36.22 270 top
CA108  10U_0603_6.3V6M~D  [C_0603]  29.5 29.68 0 bottom
CA109  10U_0603_6.3V6M~D  [C_0603]  22.39 33.23 180 top
CA110  10U_0603_6.3V6M~D  [C_0603]  21.76 24.85 0 top
CA111  0.1U_0402_16V7K~N  [C_0402]  29.82 24.11 90 bottom
CA112  10U_0805_10V6K  [C_0805]  31.22 24.43 270 bottom
CC4  12P_0402_50V8J  [C_0402]  158.6 45.68 180 bottom
CC5  12P_0402_50V8J  [C_0402]  158.6 46.57 180 bottom
CC8  33P_0402_50V8J  [C_0402]  179.86 53.68 0 bottom
CC9  0.1U_0402_25V6  [C_0402]  186.54 52.49 270 bottom
CC21  15P_0402_50V8J  [C_0402]  131.12 73.81 180 top
CC22  15P_0402_50V8J  [C_0402]  133.76 73.81 0 top
CC23  6.8P_0402_50V8J  [C_0402]  152.12 45.93 0 top
CC24  1U_0402_6.3V6K  [C_0402]  147.17 46.31 90 top
CC25  1U_0402_6.3V6K  [C_0402]  148.44 46.31 90 top
CC26  6.8P_0402_50V8J  [C_0402]  151.23 45.93 180 top
CC27  22P_0402_50V8J  [C_0402]  141.71 44.54 90 bottom
CC28  0.1U_0402_10V7K  [C_0402]  67.79 75.9 90 top
CC29  0.1U_0402_10V7K  [C_0402]  67.67 69.3 90 bottom
CC31  22U_0603_6.3V6M  [C_0603]  134.67 48.28 270 top
CC32  0.1U_0402_25V6  [C_0402]  66.78 69.3 90 bottom
CC33  0.1U_0402_25V6  [C_0402]  66.78 75.83 90 top
CC34  22U_0603_6.3V6M  [C_0603]  127.99 47.39 270 top
CC35  22U_0603_6.3V6M  [C_0603]  124.05 47.77 270 top
CC125  0.1U_0201_10V6K  [C_0201]  140.49 56.84 90 top
CC174  10U_0402_6.3V6M  [C_0402]  124.56 49.74 90 top
CC175  10U_0402_6.3V6M  [C_0402]  129.26 49.23 90 top
CC176  10U_0402_6.3V6M  [C_0402]  135.23 49.79 90 top
CC177  10U_0402_6.3V6M  [C_0402]  138.53 49.67 90 top
CC178  10U_0402_6.3V6M  [C_0402]  134.34 49.79 90 top
CC179  10U_0402_6.3V6M  [C_0402]  122.53 48.98 180 top
CC180  10U_0402_6.3V6M  [C_0402]  122.4 61.86 90 top
CC181  1U_0201_6.3V6M  [C_0201]  134.98 57.74 180 top
CC182  1U_0201_6.3V6M  [C_0201]  135.99 56.47 0 top
CC183  1U_0201_6.3V6M  [C_0201]  118.52 62.07 270 top
CC184  10U_0402_6.3V6M  [C_0402]  119.66 60.66 0 top
CC185  1U_0201_6.3V6M  [C_0201]  134.91 56.6 180 top
CC186  1U_0201_6.3V6M  [C_0201]  128.63 56.22 180 top
CC187  10U_0402_6.3V6M  [C_0402]  118.8 60.54 180 top
CC188  1U_0201_6.3V6M  [C_0201]  121.64 62.32 90 top
CC189  1U_0201_6.3V6M  [C_0201]  119.1 62.06 270 top
CC190  1U_0201_6.3V6M  [C_0201]  120.37 62.32 90 top
CC191  1U_0201_6.3V6M  [C_0201]  121.01 62.32 90 top
CC192  1U_0201_6.3V6M  [C_0201]  119.74 62.06 270 top
CC194  10U_0402_6.3V6M  [C_0402]  128.37 51.72 270 top
CC195  1U_0402_6.3V6K  [C_0402]  141.83 72.35 270 top
CC199  1U_0402_6.3V6K  [C_0402]  138.79 72.35 270 top
CC202  1U_0402_6.3V6K  [C_0402]  139.04 66.89 270 top
CC203  1U_0402_6.3V6K  [C_0402]  142.98 66.43 90 top
CC204  1U_0402_6.3V6K  [C_0402]  151.61 54.87 90 top
CC205  1U_0402_6.3V6K  [C_0402]  142.34 60.54 0 top
CC206  1U_0402_6.3V6K  [C_0402]  141.33 61.43 0 top
CC209  4.7P_0402_50V8C  [C_0402]  140.44 62.32 270 top
CC210  47U_0805_6.3V6M  [C_0805]  145.39 76.79 90 top
CC211  1U_0402_6.3V6K  [C_0402]  145.01 64.86 0 top
CC212  1U_0402_6.3V6K  [C_0402]  155.68 61.05 0 bottom
CC213  1U_0402_6.3V6K  [C_0402]  145.39 49.74 90 top
CC214  0.1U_0402_10V7K  [C_0402]  146.79 49.79 90 top
CC217  1U_0402_6.3V6K  [C_0402]  140.18 58.76 0 top
CC218  1U_0402_6.3V6K  [C_0402]  141.07 63.78 180 top
CC220  1U_0402_6.3V6K  [C_0402]  146.79 71.28 270 top
CC223  0.1U_0402_10V7K  [C_0402]  141.96 58 90 top
CC224  1U_0402_6.3V6K  [C_0402]  143.2 56.42 0 top
CC225  0.1U_0201_10V6K  [C_0201]  159 59.88 270 top
CC240  0.1U_0402_10V7K  [C_0402]  101.4 45.68 180 bottom
CC248  10U_0402_6.3V6M  [C_0402]  136.88 58.63 90 top
CC249  10U_0402_6.3V6M  [C_0402]  129.01 57.62 90 top
CC250  1U_0402_6.3V6K  [C_0402]  135.1 58.63 90 top
CC251  1U_0402_6.3V6K  [C_0402]  135.99 58.63 90 top
CC252  1U_0402_6.3V6K  [C_0402]  128.12 57.36 90 top
CC253  1U_0402_6.3V6K  [C_0402]  134.21 58.63 90 top
CC256  1U_0201_6.3V6M  [C_0201]  135.28 52.56 270 top
CC257  1U_0201_6.3V6M  [C_0201]  131.67 52.54 270 top
CC258  1U_0201_6.3V6M  [C_0201]  127.61 52.54 270 top
CC259  1U_0201_6.3V6M  [C_0201]  138.02 52.54 270 top
CC260  1U_0201_6.3V6M  [C_0201]  122.44 49.74 180 top
CC261  1U_0201_6.3V6M  [C_0201]  139.42 57.53 270 top
CC264  1U_0402_6.3V6K  [C_0402]  145.18 67.18 180 top
CC265  1U_0402_6.3V6K  [C_0402]  143.03 62.44 0 top
CC266  0.01U_0402_16V7K  [C_0402]  143.61 45.42 270 bottom
CC267  1U_0402_6.3V6K  [C_0402]  144.81 62.44 0 top
CC268  1U_0402_6.3V6K  [C_0402]  144.37 58.89 180 top
CC269  0.1U_0402_25V6  [C_0402]  68.81 75.9 90 top
CC270  0.1U_0402_10V7K  [C_0402]  144.5 49.74 90 top
CC271  47U_0805_6.3V6M  [C_0805]  155.93 44.41 90 top
CC272  47U_0805_6.3V6M  [C_0805]  153.77 60.41 270 top
CC273  47U_0805_6.3V6M  [C_0805]  143.61 76.79 90 top
CC274  47U_0805_6.3V6M  [C_0805]  141.83 76.79 90 top
CC279  22U_0603_6.3V6M  [C_0603]  158.28 43.33 270 top
CC280  22U_0603_6.3V6M  [C_0603]  157.07 43.33 270 top
CD1  1U_0402_6.3V6K~D  [C_0402]  118.05 35.41 180 top
CD2  10U_0603_6.3V6M~D  [C_0603]  99.29 35.65 180 top
CD3  1U_0402_6.3V6K~D  [C_0402]  97.35 31.58 180 top
CD4  10U_0603_6.3V6M~D  [C_0603]  97.33 29.06 180 top
CD5  1U_0402_6.3V6K~D  [C_0402]  122.5 35.41 0 top
CD6  10U_0603_6.3V6M~D  [C_0603]  125.93 35.54 180 top
CD7  1U_0402_6.3V6K~D  [C_0402]  127.83 33 90 top
CD8  10U_0603_6.3V6M~D  [C_0603]  97.45 32.98 180 top
CD29  1U_0402_6.3V6K~D  [C_0402]  112.12 30.95 90 top
CD30  10U_0603_6.3V6M~D  [C_0603]  143.61 35.54 180 top
CD33  1U_0402_6.3V6K~D  [C_0402]  100.5 35.41 0 top
CD34  10U_0603_6.3V6M~D  [C_0603]  117.45 20.41 180 bottom
CD37  1U_0402_6.3V6K~D  [C_0402]  106.85 35.41 0 top
CD38  10U_0603_6.3V6M~D  [C_0603]  161.65 27.96 270 top
CD39  0.22U_0402_10V6K  [C_0402]  186.67 27.26 180 bottom
CD41  1U_0402_6.3V6K~D  [C_0402]  119.36 20.53 180 bottom
CD42  10U_0603_6.3V6M~D  [C_0603]  127.96 27.28 270 top
CD43  0.22U_0402_10V6K  [C_0402]  186.67 28.15 180 bottom
CD44  0.22U_0402_10V6K  [C_0402]  186.67 35.77 180 bottom
CD45  0.22U_0402_10V6K  [C_0402]  186.67 29.17 180 bottom
CD46  0.22U_0402_10V6K  [C_0402]  186.67 30.06 180 bottom
CD47  0.22U_0402_10V6K  [C_0402]  186.67 34.88 180 bottom
CD51  0.22U_0402_10V6K  [C_0402]  186.67 31.96 180 bottom
CD53  0.22U_0402_10V6K  [C_0402]  186.67 31.07 180 bottom
CD57  1U_0402_6.3V6K~D  [C_0402]  146.66 31.58 270 top
CD58  10U_0603_6.3V6M~D  [C_0603]  142.34 20.41 0 bottom
CD59  1U_0402_6.3V6K~D  [C_0402]  148.89 35.41 0 top
CD60  10U_0603_6.3V6M~D  [C_0603]  157.46 35.52 0 top
CD61  1U_0402_6.3V6K~D  [C_0402]  145.64 28.79 90 top
CD62  10U_0603_6.3V6M~D  [C_0603]  136.37 20.41 0 bottom
CD63  1U_0402_6.3V6K~D  [C_0402]  130.91 33 90 top
CD64  10U_0603_6.3V6M~D  [C_0603]  150.98 20.41 180 bottom
CD85  1U_0402_6.3V6K~D  [C_0402]  135.36 20.53 180 bottom
CD86  10U_0603_6.3V6M~D  [C_0603]  110.28 35.54 180 top
CD87  1U_0402_6.3V6K~D  [C_0402]  146.66 28.79 90 top
CD88  10U_0603_6.3V6M~D  [C_0603]  157.71 20.41 0 bottom
CD89  1U_0402_6.3V6K~D  [C_0402]  141.45 20.53 180 bottom
CD90  10U_0603_6.3V6M~D  [C_0603]  130.91 26.5 90 top
CD91  1U_0402_6.3V6K~D  [C_0402]  145.77 22.44 90 top
CD92  10U_0603_6.3V6M~D  [C_0603]  97.33 26.78 180 top
CD117  0.047U_0402_10V7K~D  [C_0402]  105.33 35.39 180 top
CD118  0.047U_0402_10V7K~D  [C_0402]  120.21 35.41 180 top
CD119  0.047U_0402_10V7K~D  [C_0402]  138.4 35.41 180 top
CD120  0.047U_0402_10V7K~D  [C_0402]  153.97 35.41 180 top
CD129  1U_0402_6.3V6K~D  [C_0402]  147.68 17.69 270 top
CD132  1U_0402_6.3V6K~D  [C_0402]  107.04 17.69 270 top
CD133  1U_0402_6.3V6K~D  [C_0402]  99.8 17.69 270 top
CD135  1U_0402_6.3V6K~D  [C_0402]  117.58 17.69 270 top
CD136  1U_0402_6.3V6K~D  [C_0402]  133.07 17.69 270 top
CD139  1U_0402_6.3V6K~D  [C_0402]  141.07 17.69 270 top
CD140  1U_0402_6.3V6K~D  [C_0402]  153.65 17.69 270 top
CD142  1U_0402_6.3V6K~D  [C_0402]  124.94 17.69 270 top
CD143  1U_0402_6.3V6K~D  [C_0402]  113.01 26.76 90 top
CD144  1U_0402_6.3V6K~D  [C_0402]  161.46 30.84 90 top
CD145  1U_0402_6.3V6K~D  [C_0402]  113.13 30.95 90 top
CD146  1U_0402_6.3V6K~D  [C_0402]  97.2 25.63 180 top
CD147  10U_0603_6.3V6M~D  [C_0603]  97.38 30.44 180 top
CD148  1U_0402_6.3V6K~D  [C_0402]  112.12 33.11 90 top
CD149  1U_0402_6.3V6K~D  [C_0402]  105.77 20.66 270 top
CD150  1U_0402_6.3V6K~D  [C_0402]  112.12 28.79 90 top
CD151  1U_0402_6.3V6K~D  [C_0402]  104.88 20.66 270 top
CD152  0.1U_0402_16V7K~D  [C_0402]  103.42 35.41 180 top
CD153  0.1U_0402_16V7K~D  [C_0402]  97.2 23.73 180 top
CD154  0.1U_0402_16V7K~D  [C_0402]  127.83 23.86 90 top
CD155  0.1U_0402_16V7K~D  [C_0402]  113.13 33.11 90 top
CD156  1U_0402_6.3V6K~D  [C_0402]  122.15 20.53 0 bottom
CD157  1U_0402_6.3V6K~D  [C_0402]  127.83 28.94 90 top
CD158  1U_0402_6.3V6K~D  [C_0402]  127.83 30.84 90 top
CD159  1U_0402_6.3V6K~D  [C_0402]  115.01 35.41 0 top
CD160  1U_0402_6.3V6K~D  [C_0402]  127.83 22.59 270 top
CD161  1U_0402_6.3V6K~D  [C_0402]  113.13 28.79 90 top
CD162  1U_0402_6.3V6K~D  [C_0402]  145.64 25.61 270 top
CD163  1U_0402_6.3V6K~D  [C_0402]  145.64 30.69 90 top
CD164  1U_0402_6.3V6K~D  [C_0402]  112.12 25.23 270 top
CD165  1U_0402_6.3V6K~D  [C_0402]  146.66 26.88 90 top
CD166  0.1U_0402_16V7K~D  [C_0402]  145.64 32.85 90 top
CD167  0.1U_0402_16V7K~D  [C_0402]  136.24 35.41 180 top
CD168  0.1U_0402_16V7K~D  [C_0402]  146.66 33.74 270 top
CD169  0.1U_0402_16V7K~D  [C_0402]  161.46 32.87 90 top
CD170  1U_0402_6.3V6K~D  [C_0402]  161.46 28.94 90 top
CD171  1U_0402_6.3V6K~D  [C_0402]  152.12 20.53 0 bottom
CD172  1U_0402_6.3V6K~D  [C_0402]  156.38 35.41 180 top
CD173  1U_0402_6.3V6K~D  [C_0402]  134.08 35.41 180 top
CD174  1U_0402_6.3V6K~D  [C_0402]  130.91 28.94 90 top
CD175  1U_0402_6.3V6K~D  [C_0402]  130.91 31.73 270 top
CD176  1U_0402_6.3V6K~D  [C_0402]  140.05 35.41 0 top
CD177  1U_0402_6.3V6K~D  [C_0402]  156.69 20.53 180 bottom
CD178  1U_0402_6.3V6K~D  [C_0402]  161.46 24.11 90 top
CD179  1U_0402_6.3V6K~D  [C_0402]  151.81 35.41 180 top
CD180  0.047U_0402_10V7K~D  [C_0402]  103.99 20.66 270 top
CD181  0.047U_0402_10V7K~D  [C_0402]  120.24 20.53 0 bottom
CD182  10U_0603_6.3V6M~D  [C_0603]  128.89 23.16 0 top
CD183  0.047U_0402_10V7K~D  [C_0402]  138.79 20.53 0 bottom
CD184  0.047U_0402_10V7K~D  [C_0402]  153.9 20.53 0 bottom
CD185  0.022U_0402_16V7K~D  [C_0402]  104.12 43.52 270 top
CD186  0.022U_0402_16V7K~D  [C_0402]  105.26 40.22 180 top
CD187  0.022U_0402_16V7K~D  [C_0402]  153.01 39.2 0 top
CD196  22U_0603_6.3V6M~D  [C_0603]  158.6 17.99 270 top
CD197  22U_0603_6.3V6M~D  [C_0603]  95.61 19.26 90 top
CE3  0.1U_0402_25V6  [C_0402]  29.19 17.36 180 bottom
CE4  10U_0603_6.3V6M  [C_0603]  27.98 21.17 0 bottom
CE10  0.1U_0402_25V6  [C_0402]  29.19 16.47 180 bottom
CE13  0.047U_0402_16V4Z  [C_0402]  184.89 70.95 90 top
CE14  1U_0402_6.3V6K  [C_0402]  183.11 70.95 90 top
CE17  1U_0402_6.3V6K  [C_0402]  182.35 55.79 270 top
CE21  1U_0402_6.3V6K  [C_0402]  188.06 51.52 270 top
CE22  1U_0402_6.3V6K  [C_0402]  186.16 54.87 90 bottom
CE38  0.1U_0402_25V6  [C_0402]  190.48 64.09 0 top
CE39  2200P_0402_50V7K  [C_0402]  188.14 67.01 180 bottom
CE40  0.1U_0402_25V6  [C_0402]  181.2 70.95 90 top
CE41  0.1U_0402_25V6  [C_0402]  179.68 55.79 270 top
CE42  10U_0603_6.3V6M  [C_0603]  169.9 65.87 90 top
CE43  0.1U_0402_25V6  [C_0402]  187.17 60.36 270 bottom
CE44  0.1U_0402_25V6  [C_0402]  173.18 62.95 0 top
CE45  4.7U_0603_6.3V6K  [C_0603]  190.35 65.24 0 top
CE46  0.1U_0402_25V6  [C_0402]  170.1 61.43 180 top
CE47  100P_0402_50V8J  [C_0402]  138.96 62.29 270 top
CE48  100P_0402_50V8J  [C_0402]  106.4 45.04 90 bottom
CE49  1U_0402_6.3V6K  [C_0402]  189.84 53.3 270 top
CE50  0.1U_0402_25V6  [C_0402]  177.06 58.63 0 bottom
CE51  100P_0402_50V8J  [C_0402]  194.41 76.92 180 top
CE52  4.7P_0402_50V8C  [C_0402]  180.44 73.24 90 top
CE53  22P_0402_50V8J  [C_0402]  186.16 53.55 0 top
CE54  4700P_0402_25V7K  [C_0402]  188.01 64.47 180 bottom
CE55  0.1U_0402_25V6  [C_0402]  186.03 70.95 90 top
CE56  1U_0402_6.3V6K  [C_0402]  183.49 55.79 270 bottom
CE57  100P_0402_50V8J  [C_0402]  23.34 57.37 270 bottom
CE58  2200P_0402_50V7K  [C_0402]  189.97 67.34 270 bottom
CE59  1U_0402_6.3V6K  [C_0402]  174.22 61.38 270 bottom
CE60  2200P_0402_50V7K  [C_0402]  188.95 70.06 180 top
CE61  0.1U_0402_25V6  [C_0402]  177.98 70.06 180 top
CE62  22P_0402_50V8J  [C_0402]  185.14 53.55 180 top
CE63  0.1U_0402_25V6  [C_0402]  184 70.95 90 top
CE64  0.1U_0402_25V6  [C_0402]  183.24 55.79 270 top
CE65  0.1U_0402_25V6  [C_0402]  187.17 56.42 270 bottom
CE66  100P_0402_50V8J  [C_0402]  149.45 39.84 180 top
CE67  2200P_0402_50V7K  [C_0402]  194.16 66.58 270 top
CE68  47P_0402_50V8J~D  [C_0402]  176.94 56.47 0 bottom
CH11  0.1U_0402_10V7K~D  [C_0402]  40.49 36.03 90 bottom
CH12  0.1U_0402_10V7K~D  [C_0402]  39.47 36.03 90 bottom
CH13  0.1U_0402_10V7K~D  [C_0402]  206.48 21.04 270 bottom
CH14  0.1U_0402_10V7K~D  [C_0402]  205.46 21.04 270 bottom
CH95  1U_0402_6.3V6K~D  [C_0402]  15.04 14.56 180 top
CMOS1  SHORT PADS~D  [SHORTPADS]  148.95 42.88 270 top
CS44  0.1U_0402_10V7K  [C_0402]  189.33 38.19 180 bottom
CT1  0.22U_0201_6.3V6M  [C_0201]  46.2 67.94 270 top
CT2  0.22U_0201_6.3V6M  [C_0201]  47.47 67.36 90 top
CT3  0.22U_0201_6.3V6M  [C_0201]  46.84 67.94 270 top
CT4  0.22U_0201_6.3V6M  [C_0201]  48.11 67.36 90 top
CT5  0.22U_0201_6.3V6M  [C_0201]  44.17 67.94 270 top
CT6  0.22U_0201_6.3V6M  [C_0201]  44.81 67.36 90 top
CT7  0.22U_0201_6.3V6M  [C_0201]  43.54 67.94 270 top
CT8  0.22U_0201_6.3V6M  [C_0201]  45.44 67.36 90 top
CT9  1U_0603_25V6  [C_0603]  9.07 56.18 270 bottom
CT17  0.1U_0201_6.3V6K  [C_0201]  49.34 58 0 top
CT18  0.1U_0201_6.3V6K  [C_0201]  49.34 58.63 0 top
CT19  0.1U_0201_6.3V6K  [C_0201]  51.55 58.89 0 top
CT20  0.1U_0201_6.3V6K  [C_0201]  51.55 59.52 0 top
CT21  0.1U_0201_6.3V6K  [C_0201]  49.34 59.78 0 top
CT22  0.1U_0201_6.3V6K  [C_0201]  49.34 60.41 0 top
CT23  0.1U_0201_6.3V6K  [C_0201]  51.55 60.66 0 top
CT24  0.1U_0201_6.3V6K  [C_0201]  51.55 61.3 0 top
CT25  0.1U_0201_6.3V6K  [C_0201]  51.54 56.35 0 top
CT26  0.1U_0201_6.3V6K  [C_0201]  51.54 55.71 0 top
CT29  0.1U_0201_6.3V6K  [C_0201]  49.34 61.55 0 top
CT30  0.1U_0201_6.3V6K  [C_0201]  49.34 62.19 0 top
CT31  0.1U_0201_6.3V6K  [C_0201]  51.54 62.32 0 top
CT32  0.1U_0201_6.3V6K  [C_0201]  51.54 62.95 0 top
CT33  0.1U_0201_6.3V6K  [C_0201]  49.34 63.2 0 top
CT34  0.1U_0201_6.3V6K  [C_0201]  49.34 63.84 0 top
CT35  0.1U_0201_6.3V6K  [C_0201]  49.34 65.36 0 top
CT36  0.1U_0201_6.3V6K  [C_0201]  49.34 64.73 0 top
CT37  0.22U_0201_6.3V6M  [C_0201]  35.54 63.03 180 top
CT38  0.22U_0201_6.3V6M  [C_0201]  35.54 62.39 180 top
CT39  0.22U_0201_6.3V6M  [C_0201]  35.15 63.71 180 top
CT40  0.22U_0201_6.3V6M  [C_0201]  35.15 64.47 180 top
CT41  0.1U_0201_6.3V6K  [C_0201]  51.54 64.73 0 top
CT42  0.1U_0201_6.3V6K  [C_0201]  51.54 64.09 0 top
CT43  8.2P_0402_50V8J~D  [C_0402]  34.72 67.14 180 top
CT44  10P_0402_50V8J~D  [C_0402]  36.86 68.67 0 top
CT47  0.1U_0201_6.3V6K  [C_0201]  41.24 38.31 0 top
CT50  0.1U_0201_6.3V6K  [C_0201]  46.71 51.52 270 top
CT52  1U_0201_6.3V6M  [C_0201]  35.22 55.42 90 top
CT53  10U_0402_6.3V6M  [C_0402]  31.55 55.79 180 top
CT54  10U_0402_6.3V6M  [C_0402]  31.55 54.01 180 top
CT55  10U_0402_6.3V6M  [C_0402]  31.55 54.9 180 top
CT56  10U_0402_6.3V6M  [C_0402]  31.55 53.14 180 top
CT57  1U_0201_6.3V6M  [C_0201]  34.95 58.25 180 top
CT62  1U_0201_6.3V6M  [C_0201]  49.38 53.46 270 top
CT63  1U_0201_6.3V6M  [C_0201]  50.01 53.46 270 top
CT64  1U_0201_6.3V6M  [C_0201]  51.28 53.46 270 top
CT65  1U_0201_6.3V6M  [C_0201]  50.65 53.46 270 top
CT66  1U_0201_6.3V6M  [C_0201]  51.92 53.46 270 top
CT67  1U_0201_6.3V6M  [C_0201]  51.66 54.31 0 top
CT68  1U_0201_6.3V6M  [C_0201]  51.66 54.95 0 top
CT71  1U_0201_6.3V6M  [C_0201]  41.16 67.27 180 top
CT72  1U_0201_6.3V6M  [C_0201]  42.23 67.27 0 top
CT74  1U_0201_6.3V6M  [C_0201]  35.66 60.03 270 top
CT80  1U_0201_6.3V6M  [C_0201]  42.23 67.9 0 top
CT81  1U_0201_6.3V6M  [C_0201]  41.16 67.9 180 top
CT83  1U_0201_6.3V6M  [C_0201]  34.39 60.03 270 top
CT84  1U_0201_6.3V6M  [C_0201]  35.03 60.03 270 top
CT85  1U_0201_6.3V6M  [C_0201]  33.8 60.03 180 top
CT86  1U_0201_6.3V6M  [C_0201]  34.01 60.66 90 top
CT88  47U_0603_6.3V M  [C_0603]  31.55 49.49 180 top
CT89  47U_0603_6.3V M  [C_0603]  31.53 52.03 180 top
CT90  47U_0603_6.3V M  [C_0603]  31.53 50.76 180 top
CT91  1U_0201_6.3V6M  [C_0201]  34.65 60.66 90 top
CT92  1U_0201_6.3V6M  [C_0201]  35.28 60.66 90 top
CT93  1U_0201_6.3V6M  [C_0201]  49.34 67.52 0 top
CT94  1U_0201_6.3V6M  [C_0201]  49.34 66.89 0 top
CT95  10U_0402_6.3V6M  [C_0402]  34.39 65.31 90 top
CT96  10U_0402_6.3V6M  [C_0402]  33.5 65.31 90 top
CT97  10U_0402_6.3V6M  [C_0402]  32.61 65.31 90 top
CT98  10U_0402_6.3V6M  [C_0402]  35.28 65.31 90 top
CT99  1U_0201_6.3V6M  [C_0201]  44.17 69.97 270 top
CT100  1U_0201_6.3V6M  [C_0201]  39.73 67.36 90 top
CT101  1U_0201_6.3V6M  [C_0201]  49.34 54.57 0 top
CT102  1U_0201_6.3V6M  [C_0201]  49.34 55.33 0 top
CT103  1U_0201_6.3V6M  [C_0201]  49.34 55.97 0 top
CT107  0.1U_0201_6.3V6K  [C_0201]  51.54 57.74 0 top
CT108  0.1U_0201_6.3V6K  [C_0201]  51.54 57.11 0 top
CT144  2.2U_0402_6.3V6M  [C_0402]  24.65 66.34 90 top
CT151  4.7U_0402_6.3V6M  [C_0402]  19.66 66.37 90 top
CT152  4.7U_0402_6.3V6M  [C_0402]  28.8 65.24 180 top
CT163  1U_0201_6.3V6M  [C_0201]  24.37 52.61 0 bottom
CT164  47U_0603_6.3V M  [C_0603]  23.79 50.62 180 bottom
CT165  47U_0603_6.3V M  [C_0603]  23.58 51.89 180 bottom
CZ78  0.1U_0402_10V7K  [C_0402]  151.79 73.87 0 top
CZ82  0.1U_0402_10V7K  [C_0402]  160.81 67.52 0 top
CZ83  0.1U_0402_10V7K  [C_0402]  159.74 46.44 0 top
CZ84  1U_0402_6.3V6K  [C_0402]  158.52 78.32 0 top
CZ85  0.1U_0402_10V7K  [C_0402]  151.54 80.1 0 top
CZ86  0.1U_0402_10V7K  [C_0402]  167.54 66.89 0 top
CZ87  1U_0402_6.3V6K  [C_0402]  167.54 66 0 top
CZ88  0.1U_0402_10V7K  [C_0402]  158.52 79.21 0 top
CZ89  1U_0402_6.3V6K  [C_0402]  165.89 46.57 0 top
CZ90  0.1U_0402_10V7K  [C_0402]  46.77 49.36 180 top
CZ91  10U_0402_6.3V6M  [C_0402]  50.72 48.22 180 top
CZ92  1U_0402_6.3V6K  [C_0402]  158.47 74.38 270 top
D72  BAT54CW-7-F_SOT323-3~D  [BAT54CW-7-F_SOT323-3]  190.86 28.03 270 top
D73  BAT54CW-7-F_SOT323-3~D  [BAT54CW-7-F_SOT323-3]  190.66 30.69 270 top
D75  ESD8011MUT5G  [ESD101-B1-02ELS_TSSLP-2-4-2]  10.9 63.97 90 top
D76  ESD8011MUT5G  [ESD101-B1-02ELS_TSSLP-2-4-2]  10.9 63.33 270 top
D77  ESD8011MUT5G  [ESD101-B1-02ELS_TSSLP-2-4-2]  15.01 61.9 90 top
D78  ESD8011MUT5G  [ESD101-B1-02ELS_TSSLP-2-4-2]  8.89 59.74 90 top
D79  ESD8011MUT5G  [ESD101-B1-02ELS_TSSLP-2-4-2]  10.2 58.12 90 top
D80  ESD8011MUT5G  [ESD101-B1-02ELS_TSSLP-2-4-2]  10.2 57.49 270 top
D81  -  [RB751S40T1G_SOD523-2]  163.68 16.21 180 top
D82  ESD8011MUT5G  [ESD101-B1-02ELS_TSSLP-2-4-2]  12.95 59.35 90 top
D83  ESD8011MUT5G  [ESD101-B1-02ELS_TSSLP-2-4-2]  12.95 58.71 270 top
D84  ESD8011MUT5G  [ESD101-B1-02ELS_TSSLP-2-4-2]  10.2 63.4 90 bottom
D85  ESD8011MUT5G  [ESD101-B1-02ELS_TSSLP-2-4-2]  10.2 62.76 270 bottom
D86  ESD8011MUT5G  [ESD101-B1-02ELS_TSSLP-2-4-2]  10.35 55.57 270 top
D87  ESD8011MUT5G  [ESD101-B1-02ELS_TSSLP-2-4-2]  14.07 66.06 180 top
D88  ESD8011MUT5G  [ESD101-B1-02ELS_TSSLP-2-4-2]  10.2 57.55 270 bottom
D89  ESD8011MUT5G  [ESD101-B1-02ELS_TSSLP-2-4-2]  10.2 58.32 90 bottom
D90  ESD8011MUT5G  [ESD101-B1-02ELS_TSSLP-2-4-2]  10.2 60.79 90 bottom
D91  ESD8011MUT5G  [ESD101-B1-02ELS_TSSLP-2-4-2]  10.2 60.16 270 bottom
D94  BAT54CW-7-F_SOT323-3~D  [BAT54CW-7-F_SOT323-3]  203.43 43.71 180 top
D122  -  [BAS40-04_SOT23-3]  13.03 12.15 270 top
D123  BAT54LPS-7  [BZT52C15LP-7_DFN1006-2]  11.42 55.73 270 top
DA1  AZ5125-02S.R7G_SOT23-3  [AZ5125-02SPR7G_SOT23-3]  17.25 34.15 0 bottom
DA2  AZ5125-02S.R7G_SOT23-3  [AZ5125-02SPR7G_SOT23-3]  17.25 23.81 180 bottom
DA3  -  [PJDLC05C_SOT23-3]  20.9 15.96 270 top
DA4  -  [PJDLC05C_SOT23-3]  27.92 17.99 180 top
DA5  AZ5123-01F.R7G_DFN1006P2X2  [ESD207-B1-02EL_TSLP-2-19-2]  5.63 23.2 180 bottom
DA7  AZ5123-01F.R7G_DFN1006P2X2  [ESD207-B1-02EL_TSLP-2-19-2]  5.44 21.42 270 top
DE11  -  [RB751S40T1G_SOD523-2]  189.31 70.05 180 bottom
DI1  TVWDF1004AD0_DFN9  [IP4292CZ10-TBR_XSON10_2P5X1]  17.77 39.09 90 bottom
DI2  -  [L30ESDL5V0C3-2_SOT23-3]  18.49 44.03 90 bottom
DI3  -  [L30ESDL5V0C3-2_SOT23-3]  57.1 69.62 90 bottom
DI4  -  [L30ESDL5V0C3-2_SOT23-3]  74.12 75.27 90 bottom
DI7  AZ4024-02S_SOT23-3~D  [PESD24VS2UT_SOT23-3]  18.33 58.34 0 bottom
DZ1  -  [RB751S40T1G_SOD523-2]  45.82 44.92 90 top
DZ2  -  [RB751S40T1G_SOD523-2]  44.68 44.92 90 top
DZ3  -  [RB751S40T1G_SOD523-2]  159.11 48.22 180 bottom
FD1  FIDUCAL  [FIDUCIAL_C40M80]  16.55 69.87 0 top
FD2  FIDUCIAL  [FIDUCIAL_C40M80]  209.4 20.02 0 top
FD3  FIDUCAL  [FIDUCIAL_C40M80]  197.08 69.81 180 bottom
FD4  FIDUCIAL  [FIDUCIAL_C40M80]  18.52 20.91 180 bottom
H1  -  [H_2P0]  10.2 70.12 0 top
H3  -  [H_1P8N]  5.7 17.12 0 top
H4  -  [H_2P0]  81.96 79.8 0 top
H6  -  [H_3P3]  188.2 23.12 0 top
H7  -  [H_2P0]  129.09 13.28 0 top
H9  -  [H_2P0]  182.82 79.8 0 top
H10  -  [H_3P3]  162.8 53.85 0 top
H11  -  [H_3P3]  40.5 72.3 0 top
H12  -  [H_2P0]  10.2 17.12 0 top
H13  -  [H_2P0]  214.81 15.47 0 top
H14  -  [H_3P3]  104 53.85 0 top
H15  -  [H_3P3]  162.8 74.85 0 top
H16  -  [H_3P3]  104 74.85 0 top
H17  -  [H_3P3]  203 50.12 0 top
H18  -  [H_2P0]  52.89 13.31 0 top
H19  -  [H_2P0]  110.04 13.31 0 top
H20  -  [EMIST_SUL-12A2M_1P]  17.18 53.62 180 bottom
H21  -  [EMIST_SUL-12A2M_1P]  26.08 44.92 270 bottom
H22  -  [EMIST_SUL-12A2M_1P]  17.18 36.62 180 bottom
H23  -  [H_2P3X1P8N]  199.67 79.8 0 top
H24  -  [EMIST_SUL-12A2M_1P]  9.7 53.36 0 top
H25  -  [EMIST_SUL-12A2M_1P]  9.7 36.86 0 top
H26  -  [H_3P2X0P8]  97.6 14.4 0 top
JAPS1  ACES_50506-01841-P01  [ACES_50506-01841-P01_18P]  200.76 35.89 270 bottom
JAR1  ACES_50224-00401-001  [ACES_50224-00401-001_4P]  51.41 75.27 180 top
JBATT1  FOX_GS73091-10272-7H  [FOX_GS73091-10272-7H_9P-T]  71.1 26.14 0 bottom
JCAM  CVILU_CI1806M2HRP-NH  [CVILU_CI1806M2HRP-NH_6P]  54.1 73.63 0 bottom
JDEG1  HB_A531015-SCHR21  [HB_A531015-SCHR21_10P]  169.65 68.22 0 bottom
JEDP  ACES_50398-04041-001  [ACES_50398-04041-001_40P]  192.75 24.37 90 bottom
JFAN1  ACES_50224-00401-001  [ACES_50224-00401-001_4P]  165.62 18.37 270 bottom
JHP1  SINGA_2SJ3095-022111F  [SINGA_2SJ3095-022111F_6P-T]  11.82 25.51 270 bottom
JIO1  JXT_FP270H-061G1AM  [JXT_FP270H-061G1AM_61P]  210.21 15.54 180 bottom
JKB1  E-T_6710K-Y15M-31L  [E-T_6710K-Y15M-31L_15P]  46.92 20.36 180 bottom
JLPDE1  HB_A531015-SCHR21  [HB_A531015-SCHR21_10P]  179.65 71.22 0 bottom
JNGFF1  CONCR_213AAAA32FA  [CONCR_213AAAA32FA_67P]  31.25 38.77 0 bottom
JNGFF2  CONCR_213MAAA32FA  [CONCR_213MAAA32FA_67P-T]  183.15 23.29 90 bottom
JP100  ACES_88266-05001  [ACES_88266-05001_5P]  26.46 71.29 90 bottom
JPA1  -  [JUMP_43X39]  26.01 32.55 270 bottom
JPA2  -  [JUMP_43X39]  5.77 21.55 180 bottom
JPA3  -  [JUMP_43X39]  21.69 22.64 270 top
JRTC1  ACES_50278-00201-001  [ACES_50278-00201-001_2P]  14.59 10.64 117.2 bottom
JSPK1  ACES_50224-00401-001  [ACES_50224-00401-001_4P]  25.78 13.82 90 bottom
JTAG1  @SHORT PADS~D  [SHORTPADS]  171.3 60.79 270 bottom
JTP1  ACES_50506-00841-P01  [ACES_50506-00841-P01_8P]  186.66 19.36 180 bottom
JTS  CVILU_CI1806M2HRP-NH  [CVILU_CI1806M2HRP-NH_6P]  71.65 74.56 90 bottom
JUART  ACES_50207-00471-P01  [ACES_50207-00471-P01_4P-T]  51.03 22.17 90 bottom
JUSB2  TE_C-PT13-067  [TE_C-PT13-067_9P-T]  14.23 48.61 90 bottom
JUSBC1  JAE_DX07SA24XJ2  [JAE_DX07SA24XJ2_24P-T]  7.43 63.54 270 top
JXDP1  SAMTE_BSH-030-01-L-D-A  [SAMTE_BSH-030-01-L-D-A_60P]  78.6 73.05 180 top
L2  BLM15PX181SN1D_2P  [MURAT_BLM15PX181SN1D_2P]  23.72 20.91 270 top
L3  BLM15PX181SN1D_2P  [MURAT_BLM15PX181SN1D_2P]  25.5 20.91 270 top
L4  BLM15PX181SN1D_2P  [MURAT_BLM15PX181SN1D_2P]  28.42 20.91 180 top
L5  BLM15PX181SN1D_2P  [MURAT_BLM15PX181SN1D_2P]  30.2 21.42 270 top
L55  MCM1012B900F06BP_4P  [INPAQ_MCM1012B900F06BP_4P]  62.96 69.55 180 bottom
L56  HCM1012GH900BP  [INPAQ_HCM1012GH900BP_4P]  193.65 39.33 180 top
L57  HCM1012GH900BP  [INPAQ_HCM1012GH900BP_4P]  193.64 37.78 180 top
L58  HCM1012GH900BP  [INPAQ_HCM1012GH900BP_4P]  193.65 36.15 180 top
L59  HCM1012GH900BP  [INPAQ_HCM1012GH900BP_4P]  193.65 40.85 180 top
L60  HCM1012GH900BP  [INPAQ_HCM1012GH900BP_4P]  193.65 42.38 180 top
LA2  BLM15PX600SN1D_2P  [MURAT_BLM15PX600SN1D_2P]  31.85 26.33 90 bottom
LA3  BLM21PG600SN1D_0805~D  [MURAT_BLM21PG600SN1D_L0805_2P]  22.71 21.31 90 bottom
LA4  BLM15PX600SN1D_2P  [MURAT_BLM15PX600SN1D_2P]  28.13 24.22 0 bottom
LA6  PBY100505T-700Y-N  [CHILI_PBY100505T-600Y-N_2P]  14.83 25.91 270 bottom
LA7  PBY100505T-700Y-N  [CHILI_PBY100505T-600Y-N_2P]  20.68 23.88 270 bottom
LA14  BLM15BB220SN1D_2P  [MURAT_BLM15BB220SN1D_2P]  37.18 24.85 180 top
LED10  27-11-T1D-CP1Q1RY-3C_WHITE~D  [LED_27-11-T1D-CP1Q1RY-3C_2P]  2 8.4 90 top
LED11  27-11-T1D-CP1Q1RY-3C_WHITE~D  [LED_27-11-T1D-CP1Q1RY-3C_2P]  2 4.8 90 top
LED12  27-11-T1D-CP1Q1RY-3C_WHITE~D  [LED_27-11-T1D-CP1Q1RY-3C_2P]  2 15.6 90 top
LED13  27-11-T1D-CP1Q1RY-3C_WHITE~D  [LED_27-11-T1D-CP1Q1RY-3C_2P]  2 1.2 90 top
LED14  27-11-T1D-CP1Q1RY-3C_WHITE~D  [LED_27-11-T1D-CP1Q1RY-3C_2P]  2 12 90 top
LT1  0.60UH +-20% MND-04ABIR60M-XGL  [COILC_XFL4012-601MEC_2P]  35.57 50.94 180 top
LT14  LQM18PN1R0MFHD_2P  [CHILI_PBY160808T-300Y-N_2P]  24.99 51.03 270 bottom
LT106  HCB2012KF-121T50_0805  [TAI-T_HCB2012KF-121T50_2P]  19.91 55.95 270 top
MC3  680P_0402_50V7K~D  [C_0402]  193.02 28.53 180 top
MD9  -  [PESD5V0U2BT_SOT23-3]  181.97 14.56 0 top
MD10  -  [PESD5V0U2BT_SOT23-3]  186.03 14.56 0 top
ML6  DLW21HN900SQ2L_4P  [MURAT_DLW21HN900SQ2L_4P]  15.65 59.43 180 top
ML7  DLW21HN900SQ2L_4P  [MURAT_DLW21HN900SQ2L_4P]  12.89 60.07 180 bottom
ML9  MCM1012B900F06BP_4P  [INPAQ_MCM1012B900F06BP_4P]  79.47 75.52 180 bottom
ML10  MCM1012B900F06BP_4P  [INPAQ_MCM1012B900F06BP_4P]  37.67 36.29 180 bottom
ML11  MCM1012B900F06BP_4P  [INPAQ_MCM1012B900F06BP_4P]  23.92 44.23 180 bottom
ML12  CMMI21T-670Y-N  [MURAT_DLW21SN670HQ2L_4P]  22.21 40.58 180 bottom
ML13  CMMI21T-670Y-N  [MURAT_DLW21SN670HQ2L_4P]  23.18 38.29 180 bottom
NOREF  -  []  162.8 74.85 0 top
NOREF#2  -  []  81.96 79.8 0 top
NOREF#3  -  []  214.81 15.47 0 top
NOREF#4  -  []  30.58 -23.92 0 top
NOREF#5  -  []  10.2 17.12 0 top
NOREF#6  -  []  10.2 70.12 0 top
NOREF#7  -  []  203 50.12 0 top
NOREF#8  -  []  40.5 72.3 0 top
NOREF#9  -  []  188.2 23.12 0 top
NOREF#10  -  []  52.89 13.31 0 top
NOREF#11  -  []  49.31 26.56 0 top
NOREF#12  -  []  104 53.85 0 top
NOREF#13  -  []  129.09 13.28 0 top
NOREF#14  -  []  162.8 53.85 0 top
NOREF#15  -  []  106.66 43.03 0 top
NOREF#16  -  []  104 74.85 0 top
NOREF#17  -  []  93.8 45.9 0 top
NOREF#18  -  []  182.82 79.8 0 top
NOREF#19  -  []  110.04 13.31 0 top
NOREF#20  -  []  123.86 41.47 0 top
NOREF#21  -  []  122.82 38.68 180 bottom
NOREF#22  -  []  149.15 34.54 180 bottom
NOREF#23  -  []  138.9 39.99 180 bottom
PC100  0.01U_0402_25V7K  [C_0402]  78.21 25.87 270 bottom
PC101  1000P_0402_50V7K  [C_0402]  75.67 22.82 270 bottom
PC102  2200P_0402_50V7K  [C_0402]  70.59 18.17 90 top
PC103  1000P_0603_50V7K  [C_0603]  26.01 78.32 270 top
PC104  1000P_0402_50V7K  [C_0402]  24.87 78.19 270 top
PC105  100P_0402_50V8J  [C_0402]  23.98 78.19 270 top
PC106  1000P_0402_50V7K  [C_0402]  33.12 77.86 90 bottom
PC107  100P_0402_50V8J  [C_0402]  31.73 77.81 90 bottom
PC108  10U_0805_25V6K  [C_0805]  27.48 76.52 270 top
PC200  0.022U_0603_50V7K  [C_0603]  52.93 52.85 270 top
PC201  0.022U_0603_50V7K  [C_0603]  30.58 76.73 270 bottom
PC202  0.022U_0603_50V7K  [C_0603]  35.98 77.81 180 bottom
PC203  0.1U_0402_25V7K  [C_0402]  60.81 59.91 270 bottom
PC204  220P_0402_50V7K  [C_0402]  91.34 74.63 0 top
PC205  1000P_0402_50V7K  [C_0402]  91.34 71.84 0 top
PC206  0.022U_0603_50V7K  [C_0603]  49.38 75.21 270 bottom
PC207  0.022U_0603_50V7K  [C_0603]  49.31 77.75 90 bottom
PC208  0.022U_0603_50V7K  [C_0603]  44.3 78.51 270 top
PC209  1U_0603_25V6  [C_0603]  66.78 67.71 270 bottom
PC210  1U_0402_16V6K  [C_0402]  55.73 70.77 270 top
PC211  100P_0402_50V8J  [C_0402]  84.43 73.16 90 top
PC212  1200P_0402_50V7K  [C_0402]  84.94 70.77 270 top
PC213  0.01U_0402_25V7K  [C_0402]  87.48 67.83 90 top
PC214  220P_0402_50V7K  [C_0402]  62.41 15.33 180 top
PC215  1200P_0402_50V7K  [C_0402]  64.03 18.25 0 top
PC216  220P_0402_50V7K  [C_0402]  56.95 16.6 180 top
PC217  1200P_0402_50V7K  [C_0402]  56.95 19.52 180 top
PC218  0.01U_0402_25V7K  [C_0402]  57.13 36.53 180 top
PC301  2200P_0402_50V7K  [C_0402]  50.9 36.28 0 top
PC302  22U_0805_25V6M  [C_0805]  51.03 34.88 0 top
PC303  22U_0805_25V6M  [C_0805]  51.03 33.11 0 top
PC304  22U_0805_25V6M  [C_0805]  51.03 31.33 0 top
PC305  22U_0805_25V6M  [C_0805]  51.03 33.11 0 bottom
PC306  22U_0805_25V6M  [C_0805]  51.03 34.88 0 bottom
PC307  22U_0805_25V6M  [C_0805]  51.03 31.33 0 bottom
PC309  1U_0603_25V6K  [C_0603]  44.87 22.69 180 bottom
PC310  0.1U_0402_25V6  [C_0402]  43.54 23.83 90 bottom
